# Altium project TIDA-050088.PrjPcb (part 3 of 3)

## Sheet TIDA-050088_Hardware.SchDoc
size 431 x 279 mm; Date: Not shown in title block; ApprovedBy: Not shown in title block; CheckedBy: Not shown in title block; Author: Not shown in title block; CompanyName: Not shown in title block; Engineer: Not shown in title block; Organization: Not shown in title block; Address1: Not shown in title block; Address2: Not shown in title block; Address3: Not shown in title block; Address4: Not shown in title block; DocumentNumber: 3; Revision: Use project parameter SCH_Rev; SheetNumber: 7; SheetTotal: 7; PageSetup: Record=PageOptions¦CenterHorizontal=True¦CenterVertical=True¦PrintScale=1.00¦XCorrection=1.00¦YCorrection=1.00¦PrintKind=0¦BorderSize=5000000¦LeftOffset=0¦BottomOffset=0¦Orientation=2¦PaperLength=1000¦PaperWidth=1000¦Scale=100¦PaperSource=15¦PrintQuality=600¦MediaType=1¦DitherType=10¦PaperKind=Letter¦PrintScaleMode=1
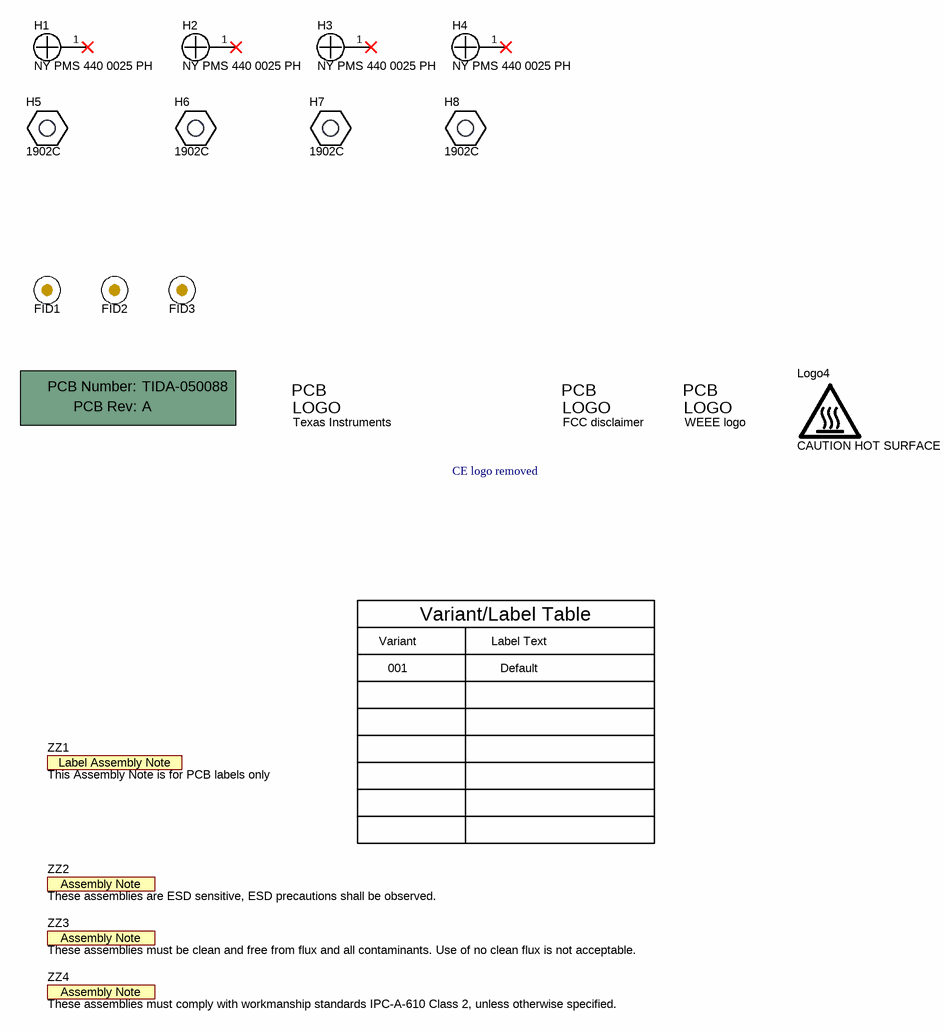
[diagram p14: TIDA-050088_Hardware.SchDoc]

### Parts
!PCB1  Printed Circuit Board  (value not drawn)  (mechanical)
FID1  Fiducial  [Fiducial10-20]  (value not drawn)
FID2  Fiducial  [Fiducial10-20]  (value not drawn)
FID3  Fiducial  [Fiducial10-20]  (value not drawn)
H1  NY PMS 440 0025 PH  [NY PMS 440 0025 PH]
H2  NY PMS 440 0025 PH  [NY PMS 440 0025 PH]
H3  NY PMS 440 0025 PH  [NY PMS 440 0025 PH]
H4  NY PMS 440 0025 PH  [NY PMS 440 0025 PH]
H5  1902C  [Keystone_1902C]
H6  1902C  [Keystone_1902C]
H7  1902C  [Keystone_1902C]
H8  1902C  [Keystone_1902C]
Logo1  Texas Instruments  [TI_Stacked_Overlay_Small]  (no BOM)
Logo2  FCC disclaimer  [FCC_disclaimer]  (no BOM)
Logo3  WEEE logo  [WEEE_Minimum]  (no BOM)
Logo4  CAUTION HOT SURFACE  [IEC_HotSurface_Medium]  (no BOM)
ZZ1  This Assembly Note is for PCB labels only  [AssemblyNoteLabel]  (no BOM)
ZZ2  These assemblies are ESD sensitive, ESD precautions shall be observed.  [AssemblyNote]  (no BOM)
ZZ3  These assemblies must be clean and free from flux and all contaminants. Use of no clean flux is not acceptable.  [AssemblyNote]  (no BOM)
ZZ4  These assemblies must comply with workmanship standards IPC-A-610 Class 2, unless otherwise specified.  [AssemblyNote]  (no BOM)

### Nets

Not connected (* = marked no-connect by the designer): H1 1*; H2 1*; H3 1*; H4 1*

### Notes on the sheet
- CE logo removed
- Variant
- Variant/Label Table
- Label Text
- 001
- Default

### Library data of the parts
!PCB1 = CMP-0003618-2: Manufacturer: Any; PartNumber: TIDA-050088
FID1-FID3 = CMP-0077181-1: Fiducial mark.  There is nothing to buy or mount.
H1-H4 = CMP-0003617-1: Machine Screw, Round, #4-40 x 1/4, Nylon, Philips panhead; Manufacturer: B&F Fastener Supply; CompType: Hardware
H5-H8 = CMP-0003610-1: Standoff, Hex, 0.5"L #4-40 Nylon; Manufacturer: Keystone; CompType: Hardware
Logo1 = CMP-0074838-1: Texas Instrument Corporate Signature; SymbolCreator: a0412235; Lib Reference: TI_Logo; Library Reference: Logo
Logo2 = CMP-0074847-1: FCC_disclaimer; Library Reference: Logo
Logo3 = CMP-0074769-1
Logo4 = CMP-0074837-2: IEC 61010-1 Hot Surface Warning; Manufacturer: Texas Instruments; CompType: IC; AEC Category: Q200; SymbolCreator: a0412235
ZZ1 = CMP-0003616-3
ZZ2 = CMP-0077236-1
ZZ3 = CMP-0077237-1
ZZ4 = CMP-0077238-1

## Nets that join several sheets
GND: TIDA-050088_Core (117 pins), TIDA-050088_Sequencing (62 pins), TIDA-050088_LDOs (158 pins), TIDA-050088_Bucks (160 pins), TIDA-050088_Aux (6 pins)
0V8: TIDA-050088_Core (57 pins), TIDA-050088_Sequencing (R48.2 R76.2)
0V92: TIDA-050088_Sequencing (R62.2 U11.5), TIDA-050088_LDOs (14 pins)
1V2: TIDA-050088_Sequencing (R66.2 U12.5), TIDA-050088_Bucks (12 pins)
1V2_MEM: TIDA-050088_LDOs (5 pins), TIDA-050088_Bucks (11 pins)
1V2_VCCO: TIDA-050088_Sequencing (U10.5), TIDA-050088_LDOs (6 pins), TIDA-050088_Bucks (11 pins)
1V5: TIDA-050088_Sequencing (R49.2 U7.5), TIDA-050088_LDOs (15 pins)
1V5_GTY: TIDA-050088_Sequencing (R64.2 U8.5), TIDA-050088_LDOs (14 pins)
2V5_DDR: TIDA-050088_LDOs (12 pins), TIDA-050088_Bucks (11 pins)
3V3_VCCO: TIDA-050088_Sequencing (R46.2 U6.5), TIDA-050088_LDOs (9 pins), TIDA-050088_Bucks (22 pins)
5V0_SYS: TIDA-050088_Sequencing (24 pins), TIDA-050088_LDOs (6 pins)
12V0_SYS: TIDA-050088_Core (32 pins), TIDA-050088_Sequencing (7 pins), TIDA-050088_LDOs (C139.1 C140.1 R111.1 U17.1), TIDA-050088_Bucks (31 pins), TIDA-050088_Aux (R115.2)
EN_0V80: TIDA-050088_Core (R19.1 U1.8), TIDA-050088_Sequencing (R45.2 TP25.1 U9.1)
EN_0V92: TIDA-050088_Sequencing (R61.2 TP30.1 U11.3), TIDA-050088_LDOs (U15.4)
EN_1V2: TIDA-050088_Sequencing (R65.2 TP32.1 U12.3), TIDA-050088_Bucks (U18.18)
EN_1V2_MEM: TIDA-050088_Sequencing (R42.2 TP22.1), TIDA-050088_Bucks (U20.18)
EN_1V2_VCCO: TIDA-050088_Sequencing (R40.2 TP20.1 U10.3), TIDA-050088_Bucks (U19.18)
EN_1V5: TIDA-050088_Sequencing (R47.2 TP26.1 U7.3), TIDA-050088_LDOs (U14.4)
EN_1V5_GTY: TIDA-050088_Sequencing (R63.2 TP31.1 U8.3), TIDA-050088_LDOs (U13.4)
EN_2V5_DDR: TIDA-050088_Sequencing (R41.2 TP21.1), TIDA-050088_Bucks (U21.18)
EN_3V3_VCCO: TIDA-050088_Sequencing (R39.2 TP19.1 U6.3), TIDA-050088_Bucks (U22.18)
EN_DDR_VTT: TIDA-050088_Sequencing (R43.2 TP24.1), TIDA-050088_LDOs (U16.17 U16.18 U16.19 U16.20)
PGOOD_6003_0V8: TIDA-050088_Core (U2.22), TIDA-050088_Sequencing (R54.1)
SYS_READY: TIDA-050088_Sequencing (U5.13), TIDA-050088_Aux (R116.2)
SYS_RESTART: TIDA-050088_Sequencing (6 pins), TIDA-050088_Aux (SW2.1 SW2.3)
SYS_SEQ_DOWN: TIDA-050088_Sequencing (R74.1 R75.2 U5.16), TIDA-050088_Aux (SW3.1 SW3.3)

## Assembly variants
001: not fitted C18 C19 C37 C38 C38 C40 C51 C60 C68 C79 C84 C91 C93 C98 C102 C111 C119 C120 FID1 FID2 FID3 R11 R14 R17 R20 R22 R39 R41 R76 R77 R87 R93 R94 R112 R134 R135 R136 R137 R?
